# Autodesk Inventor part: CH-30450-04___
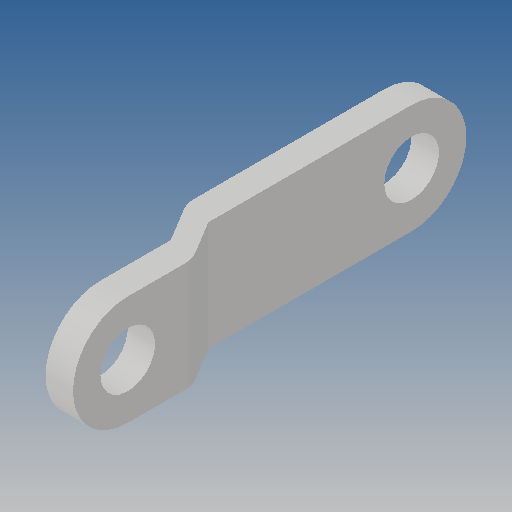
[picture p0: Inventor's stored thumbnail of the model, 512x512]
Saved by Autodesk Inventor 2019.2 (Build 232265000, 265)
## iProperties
Created: 2010-06
Part Number: CH-30450-04___
Material: Ogólny
Document SubType Name: Modeling
Designer: CADENGINEERING4
Density: 1 g/cm^3
Appearance: Domyślna
Author: CADENGINEERING4
Revision Number: ANY
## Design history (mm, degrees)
feature "NONE"
node "Bryła1"
